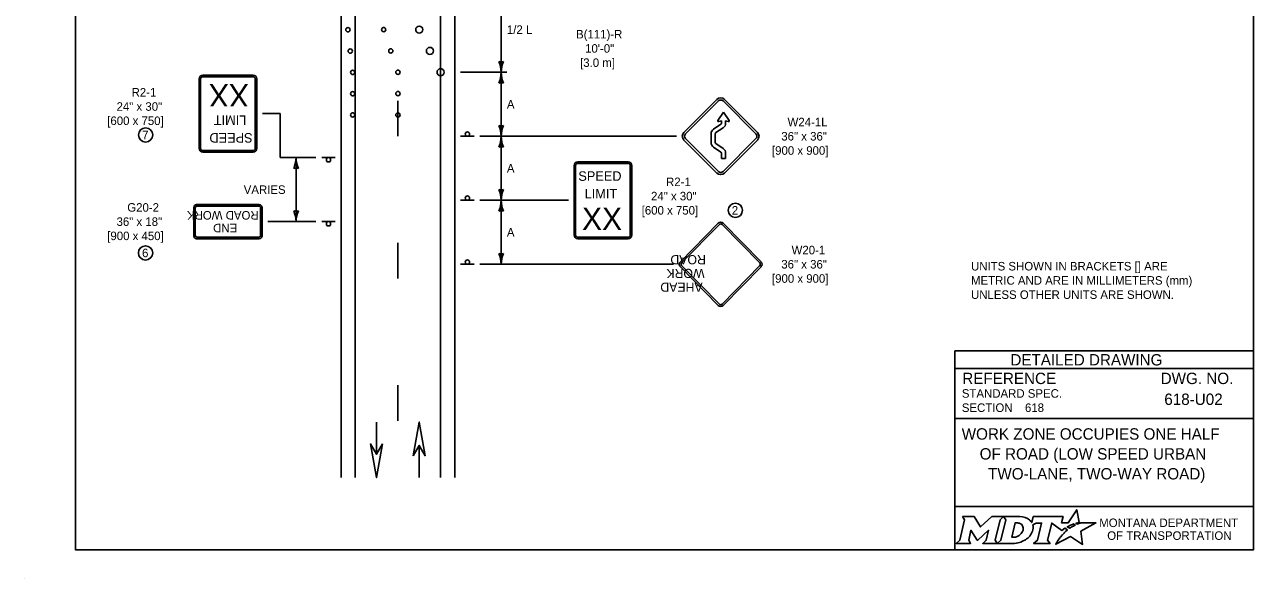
# Model space of a CAD drawing. Extents: x 49991.4 to 50021, y 49987.6 to 50011.4.
# Drawn here: x 49999.98 to 50008.61, y 49999.86 to 50003.76 of the extents above; entities that cross this region are included whole.
import ezdxf

# ---------------------------------------------------------------- set-up
doc = ezdxf.new("R2010")
doc.units = 0
for name, color, linetype in [('Level 1', 7, 'Continuous'), ('Level 2', 7, 'Continuous'), ('Level 3', 7, 'Continuous')]:
    doc.layers.add(name, color=color, linetype=linetype)

msp = doc.modelspace()

# ---------------------------------------------------------------- linework, layer by layer
at = {"layer": 'Level 1'}
for p, q in [((50002.201, 50000.5714), (50002.201, 50010.7538)), ((50002.301, 50000.5714), (50002.301, 50010.7538)), ((50003.001, 50000.5714), (50003.001, 50010.7538)), ((50002.901, 50000.5714), (50002.901, 50004.4714)), ((50001.2291, 50003.4006), (50001.5835, 50003.4006)), ((50001.2038, 50002.8858), (50001.2038, 50003.3753)), ((50001.2143, 50002.8858), (50001.2143, 50003.3753)), ((50001.2291, 50003.39), (50001.5835, 50003.39)), ((50001.5983, 50003.3753), (50001.5983, 50002.8858)), ((50001.6088, 50003.3753), (50001.6088, 50002.8858)), ((50002.601, 50002.9716), (50002.601, 50003.2216)), ((50004.8504, 50003.0834), (50004.8898, 50003.1407)), ((50004.8898, 50003.1407), (50004.9292, 50003.0834)), ((50004.819, 50003.0218), (50004.8711, 50003.0567)), ((50004.8748, 50003.0798), (50004.8571, 50003.0743)), ((50004.8748, 50003.0637), (50004.8748, 50003.0798)), ((50004.9225, 50003.0743), (50004.9048, 50003.0798)), ((50004.9048, 50003.0798), (50004.9048, 50003.0637)), ((50003.137, 50002.9714), (50003.041, 50002.9714)), ((50004.8019, 50002.9275), (50004.802, 50002.9898)), ((50004.8319, 50002.9898), (50004.8319, 50002.9274)), ((50004.8877, 50003.0318), (50004.8356, 50002.9969)), ((50004.8711, 50002.86), (50004.8187, 50002.8956)), ((50004.8356, 50002.9204), (50004.8879, 50002.8848)), ((50001.5835, 50002.8711), (50001.2291, 50002.8711)), ((50001.5835, 50002.8605), (50001.2291, 50002.8605)), ((50001.4063, 50002.8605), (50001.4063, 50002.8605)), ((50002.065, 50002.8211), (50002.161, 50002.8211)), ((50003.8649, 50002.7914), (50004.2194, 50002.7914)), ((50004.0421, 50002.7914), (50004.0421, 50002.7914)), ((50004.8748, 50002.8146), (50004.8748, 50002.8526)), ((50004.9048, 50002.8146), (50004.8748, 50002.8146)), ((50004.9048, 50002.8535), (50004.9048, 50002.8146)), ((50003.8396, 50002.2766), (50003.8396, 50002.7661)), ((50003.8502, 50002.2766), (50003.8502, 50002.7661)), ((50003.8649, 50002.7809), (50004.2194, 50002.7809)), ((50004.2341, 50002.7661), (50004.2341, 50002.2766)), ((50004.2447, 50002.7661), (50004.2447, 50002.2766)), ((50001.1661, 50002.2711), (50001.1661, 50002.4711)), ((50001.1761, 50002.2761), (50001.1761, 50002.4661)), ((50001.1862, 50002.4912), (50001.6262, 50002.4912)), ((50001.1911, 50002.4811), (50001.6211, 50002.4811)), ((50001.6361, 50002.4661), (50001.6361, 50002.2761)), ((50001.6461, 50002.4711), (50001.6461, 50002.2711)), ((50003.137, 50002.5214), (50003.041, 50002.5214)), ((50002.065, 50002.3711), (50002.161, 50002.3711)), ((50004.5865, 50002.0895), (50004.8517, 50002.3602)), ((50004.888, 50002.3602), (50005.1532, 50002.0895)), ((50004.5953, 50002.0809), (50004.8605, 50002.3515)), ((50004.8791, 50002.3515), (50005.1443, 50002.0809)), ((50001.1861, 50002.2511), (50001.6261, 50002.2511)), ((50001.1911, 50002.2611), (50001.6211, 50002.2611)), ((50002.601, 50001.9716), (50002.601, 50002.2216)), ((50004.2194, 50002.2619), (50003.8649, 50002.2619)), ((50004.2194, 50002.2513), (50003.8649, 50002.2513)), ((50003.137, 50002.0714), (50003.041, 50002.0714)), ((50004.8517, 50001.7826), (50004.5865, 50002.0533)), ((50004.8605, 50001.7913), (50004.5953, 50002.062)), ((50005.1443, 50002.062), (50004.8791, 50001.7913)), ((50005.1532, 50002.0533), (50004.888, 50001.7826)), ((50002.601, 50000.9716), (50002.601, 50001.2216)), ((50002.4507, 50000.9615), (50002.4507, 50000.7356)), ((50002.451, 50000.9615), (50002.451, 50000.7356)), ((50002.7504, 50000.5714), (50002.7504, 50000.7973)), ((50002.7507, 50000.5714), (50002.7507, 50000.7973)), ((49999.9766, 49999.8624), (49999.9766, 49999.8624))]:
    msp.add_line(p, q, dxfattribs=at)
for points in [[(50008.6146, 50011.2628), (50000.3356, 50011.2628), (50000.3356, 50000.0624), (50008.6146, 50000.0624)], [(50002.7087, 50000.725), (50002.7504, 50000.9615), (50002.7923, 50000.725), (50002.7504, 50000.7972)], [(50002.4927, 50000.8079), (50002.451, 50000.5714), (50002.4091, 50000.8079), (50002.451, 50000.7357)]]:
    msp.add_lwpolyline(points, close=True, dxfattribs=at)
for points in [[(50004.8429, 50003.2298), (50004.6113, 50002.9983)], [(50005.1283, 50002.9983), (50004.8967, 50003.2298)], [(50004.8533, 50003.2195), (50004.6217, 50002.9879)], [(50005.1179, 50002.9879), (50004.8864, 50003.2195)], [(50004.6113, 50002.9444), (50004.8429, 50002.7129)], [(50004.6217, 50002.9548), (50004.8533, 50002.7233)], [(50004.8864, 50002.7233), (50005.1179, 50002.9548)], [(50004.8967, 50002.7129), (50005.1283, 50002.9444)]]:
    msp.add_lwpolyline(points, dxfattribs=at)
for centre, radius in [((50002.751, 50003.7214), 0.025), ((50002.2493, 50003.7206), 0.015), ((50002.501, 50003.7214), 0.015), ((50002.266, 50003.5706), 0.015), ((50002.551, 50003.5714), 0.015), ((50002.826, 50003.5714), 0.025), ((50002.2827, 50003.4206), 0.015), ((50002.601, 50003.4214), 0.015), ((50002.901, 50003.4214), 0.025), ((50002.2827, 50003.2706), 0.015), ((50002.601, 50003.2714), 0.015), ((50002.2827, 50003.1214), 0.015), ((50002.601, 50003.1214), 0.015), ((50003.089, 50002.9867), 0.0152), ((50002.113, 50002.8059), 0.0152), ((50003.089, 50002.5367), 0.0152), ((50002.113, 50002.3559), 0.0152), ((50003.089, 50002.0866), 0.0152)]:
    msp.add_circle(centre, radius, dxfattribs=at)
for centre, radius, start, end in [((50002.751, 50003.7214), 0.025, 0, 180), ((50002.751, 50003.7214), 0.025, 180, 0), ((50002.826, 50003.5714), 0.025, 0, 180), ((50002.826, 50003.5714), 0.025, 180, 0), ((50001.2291, 50003.3753), 0.0253, 90, 180), ((50001.5835, 50003.3753), 0.0253, 360, 90), ((50002.901, 50003.4214), 0.025, 0, 180), ((50002.901, 50003.4214), 0.025, 180, 0), ((50001.2291, 50003.3753), 0.0148, 90, 180), ((50001.5835, 50003.3753), 0.0148, 360, 90), ((50004.8698, 50003.2029), 0.0381, 45, 135), ((50004.8698, 50003.2029), 0.0234, 45, 135), ((50004.8553, 50003.08), 0.00599, 145.48372, 287.36184), ((50004.8663, 50003.0637), 0.0085, 303.82394, 360), ((50004.8663, 50003.0637), 0.0384, 303.82395, 0), ((50004.9242, 50003.08), 0.00599, 252.63816, 34.51628), ((50004.6383, 50002.9714), 0.0381, 135, 225), ((50004.6383, 50002.9714), 0.0234, 135, 225), ((50004.8404, 50002.9898), 0.0384, 123.82394, 180), ((50004.8404, 50002.9898), 0.0085, 123.82391, 180), ((50005.1014, 50002.9714), 0.0234, 315, 45), ((50005.1014, 50002.9714), 0.0381, 315, 45), ((50001.2291, 50002.8858), 0.0253, 180, 270), ((50001.2291, 50002.8858), 0.0148, 180, 270), ((50001.5835, 50002.8858), 0.0148, 270, 360), ((50001.5835, 50002.8858), 0.0253, 270, 360), ((50004.8404, 50002.9274), 0.0384, 179.95178, 235.79051), ((50004.8404, 50002.9274), 0.0085, 179.94863, 235.79049), ((50004.8663, 50002.853), 0.0384, 0, 55.79052), ((50003.8649, 50002.7661), 0.0253, 90, 180), ((50004.2194, 50002.7661), 0.0253, 0, 90), ((50004.8663, 50002.853), 0.0085, 357.23622, 55.79052), ((50003.8649, 50002.7661), 0.0148, 90, 180), ((50004.2194, 50002.7661), 0.0148, 0, 90), ((50004.8698, 50002.7398), 0.0381, 225, 315), ((50004.8698, 50002.7398), 0.0234, 225, 315), ((50001.1862, 50002.4711), 0.02, 90, 180), ((50001.1911, 50002.4661), 0.015, 90, 180), ((50001.6211, 50002.4661), 0.015, 360, 90), ((50001.6262, 50002.4711), 0.02, 360, 90), ((50001.1911, 50002.2761), 0.015, 180, 270), ((50001.6211, 50002.2761), 0.015, 270, 360), ((50003.8649, 50002.2766), 0.0253, 180, 270), ((50003.8649, 50002.2766), 0.0148, 180, 270), ((50004.2194, 50002.2766), 0.0148, 270, 360), ((50004.2194, 50002.2766), 0.0253, 270, 360), ((50001.1861, 50002.2711), 0.02, 180, 270), ((50001.6261, 50002.2711), 0.02, 270, 360)]:
    msp.add_arc(centre, radius, start, end, dxfattribs=at)
for centre, major_axis, ratio, start_param, end_param in [((50004.8698, 50002.342), (0, 0.0258), 0.98963, 5.497787, 7.068583), ((50004.8698, 50002.342), (0, 0.0134), 0.98, 5.497787, 7.068583), ((50004.6046, 50002.0714), (0, 0.0258), 0.98963, 0.785394, 2.356194), ((50004.6046, 50002.0714), (0, 0.0134), 0.98, 0.785394, 2.356194), ((50005.1351, 50002.0714), (0, 0.0134), 0.98, 3.926991, 5.497787), ((50005.1351, 50002.0714), (0, 0.0258), 0.98963, 3.926991, 5.497787), ((50004.8698, 50001.8007), (0, -0.0258), 0.98963, 5.497795, 7.068583), ((50004.8698, 50001.8007), (0, -0.0134), 0.98, 5.497795, 7.068583)]:
    msp.add_ellipse(centre, major_axis=major_axis, ratio=ratio, start_param=start_param, end_param=end_param, dxfattribs=at)
at = {"layer": 'Level 2'}
for p, q in [((50008.6146, 50001.4624), (50006.5146, 50001.4624)), ((50006.5146, 50001.4624), (50006.5146, 50000.0624)), ((50008.6146, 50001.3374), (50006.5146, 50001.3374)), ((50008.2507, 50001.1223), (50008.2507, 50001.1223)), ((50008.6146, 50000.9874), (50006.5146, 50000.9874)), ((50007.0089, 50001.0629), (50007.0089, 50001.0629)), ((50007.5646, 50000.7383), (50007.5646, 50000.7383)), ((50008.6146, 50000.3693), (50006.5146, 50000.3693))]:
    msp.add_line(p, q, dxfattribs=at)
for points in [[(50006.5701, 50000.2974), (50006.5842, 50000.274), (50006.5507, 50000.1307), (50006.525, 50000.1082), (50006.6266, 50000.1082), (50006.6131, 50000.131), (50006.6293, 50000.2011), (50006.673, 50000.1321), (50006.6783, 50000.1321), (50006.7534, 50000.2016), (50006.737, 50000.1305), (50006.7123, 50000.1085), (50006.8139, 50000.1085), (50006.8001, 50000.1318), (50006.8333, 50000.2742)], [(50006.8333, 50000.2742), (50006.8586, 50000.2974), (50006.7762, 50000.2974), (50006.6966, 50000.2244), (50006.6521, 50000.2971), (50006.5701, 50000.2974)], [(50006.9722, 50000.2974), (50006.8586, 50000.2974), (50006.8733, 50000.2745), (50006.8394, 50000.1307), (50006.8139, 50000.1085), (50006.9245, 50000.1085)], [(50007.3771, 50000.2447), (50007.3668, 50000.2503), (50007.3784, 50000.2531), (50007.39, 50000.2551), (50007.3726, 50000.3452), (50007.3131, 50000.2539), (50007.2658, 50000.2532), (50007.2761, 50000.2973), (50007.0669, 50000.2974), (50007.0568, 50000.2549), (50007.051, 50000.2632)], [(50006.9962, 50000.2107), (50006.995, 50000.2026), (50006.9918, 50000.1933), (50006.9876, 50000.1851), (50006.982, 50000.1776), (50006.9755, 50000.1707), (50006.9676, 50000.1644), (50006.9593, 50000.1597), (50006.9502, 50000.1558), (50006.9411, 50000.1535), (50006.9319, 50000.1526), (50006.916, 50000.1526), (50006.9396, 50000.2526), (50006.9556, 50000.2526), (50006.9632, 50000.252), (50006.9708, 50000.2501), (50006.9774, 50000.2471), (50006.9835, 50000.2429), (50006.9883, 50000.2379), (50006.992, 50000.2319), (50006.9947, 50000.2257), (50006.9963, 50000.2183), (50006.9963, 50000.2153), (50006.9962, 50000.2107)], [(50007.0636, 50000.2383), (50007.0882, 50000.2514), (50007.1251, 50000.2514), (50007.0965, 50000.1309), (50007.069, 50000.1082), (50007.1852, 50000.1082), (50007.1682, 50000.1311), (50007.1964, 50000.2513), (50007.2677, 50000.1996), (50007.2888, 50000.2147), (50007.3085, 50000.2038)], [(50007.2527, 50000.1479), (50007.2374, 50000.1235), (50007.2327, 50000.116), (50007.2269, 50000.1074), (50007.2246, 50000.1031), (50007.3299, 50000.1562), (50007.4138, 50000.1011), (50007.4007, 50000.1938), (50007.5076, 50000.2522), (50007.4583, 50000.253), (50007.4282, 50000.2534), (50007.4074, 50000.2537), (50007.4006, 50000.2522), (50007.3957, 50000.251), (50007.3873, 50000.2487), (50007.3771, 50000.2447)], [(50007.3267, 50000.2171), (50007.3243, 50000.2154), (50007.306, 50000.225), (50007.3163, 50000.2307), (50007.3204, 50000.2329), (50007.329, 50000.2369), (50007.3347, 50000.2395), (50007.3426, 50000.2425), (50007.3499, 50000.2452), (50007.3617, 50000.2378), (50007.3577, 50000.2357), (50007.3531, 50000.2332), (50007.3489, 50000.231), (50007.3439, 50000.2281), (50007.342, 50000.227), (50007.3393, 50000.2254), (50007.3368, 50000.224), (50007.3345, 50000.2224), (50007.3319, 50000.2206), (50007.3292, 50000.2188), (50007.3267, 50000.2171)], [(50006.9702, 50000.1158), (50006.9786, 50000.1184), (50006.9916, 50000.1238), (50007.012, 50000.1348)], [(50007.2666, 50000.164), (50007.2666, 50000.164)]]:
    msp.add_lwpolyline(points, dxfattribs=at)
for centre, radius in [((50000.8271, 50002.9806), 0.05), ((50000.8271, 50002.9806), 0.05), ((50004.9733, 50002.4507), 0.0501), ((50000.827, 50002.151), 0.0501)]:
    msp.add_circle(centre, radius, dxfattribs=at)
for centre, radius, start, end in [((50006.9953, 50000.219), 0.0709, 339.53292, 15.85821), ((50006.9513, 50000.2363), 0.1183, 300.91025, 339.13831)]:
    msp.add_arc(centre, radius, start, end, dxfattribs=at)
for centre, major_axis, ratio, start_param, end_param in [((50006.9701, 50000.25), (0.0834, -0.0037), 0.568097, 0.61298, 1.570796), ((50007.0257, 50000.2573), (0.0361, -0.0295), 0.469099, 1.225588, 1.570796), ((50007.2974, 50000.1941), (-0.0112, -0.0097), 0.021651, 3.157348, 6.283185), ((50006.9248, 50000.2568), (0, 0.1484), 0.987302, 3.139398, 3.456847), ((50007.2597, 50000.1559), (-0.00694, -0.00806), 0.008222, 0, 3.137361), ((50007.2764, 50000.1742), (-0.0098, -0.0102), 0.016458, 3.141593, 6.279097)]:
    msp.add_ellipse(centre, major_axis=major_axis, ratio=ratio, start_param=start_param, end_param=end_param, dxfattribs=at)
at = {"layer": 'Level 3'}
for p, q in [((50003.327, 50003.4214), (50003.327, 50004.0214)), ((50003.041, 50003.4214), (50003.367, 50003.4214)), ((50003.327, 50002.9714), (50003.327, 50003.4214)), ((50001.6488, 50003.1306), (50001.7725, 50003.1306)), ((50001.7725, 50002.8211), (50001.7725, 50003.1306)), ((50003.177, 50002.9714), (50004.5602, 50002.9714)), ((50003.327, 50002.5214), (50003.327, 50002.9714)), ((50002.025, 50002.8211), (50001.7725, 50002.8211)), ((50001.885, 50002.3711), (50001.885, 50002.8211)), ((50003.177, 50002.5214), (50003.7996, 50002.5214)), ((50003.327, 50002.0714), (50003.327, 50002.5214)), ((50002.025, 50002.3711), (50001.6861, 50002.3711)), ((50003.177, 50002.0714), (50004.5391, 50002.0714))]:
    msp.add_line(p, q, dxfattribs=at)
for centre, radius, start, end in [((50003.327, 50003.5496), 0.0548, 252.13882, 287.86118), ((50003.0943, 50003.4099), 0.233, 2.82731, 22.07716), ((50003.5491, 50003.4122), 0.2223, 157.45601, 177.63952), ((50003.1049, 50003.4305), 0.2223, 337.45601, 357.63952), ((50003.5597, 50003.4329), 0.233, 182.82731, 202.07716), ((50003.327, 50003.2932), 0.0548, 72.13882, 107.86118), ((50003.327, 50003.0996), 0.0548, 252.13882, 287.86118), ((50003.0943, 50002.9599), 0.233, 2.82731, 22.07716), ((50003.1049, 50002.9805), 0.2223, 337.45601, 357.63952), ((50003.5491, 50002.9622), 0.2223, 157.45601, 177.63952), ((50003.5597, 50002.9829), 0.233, 182.82731, 202.07716), ((50003.327, 50002.8432), 0.0548, 72.13882, 107.86118), ((50001.6523, 50002.8326), 0.233, 337.92284, 357.17269), ((50002.1071, 50002.8303), 0.2223, 182.36048, 202.54399), ((50001.885, 50002.6929), 0.0548, 72.13882, 107.86118), ((50003.327, 50002.6496), 0.0548, 252.13882, 287.86118), ((50003.0943, 50002.5099), 0.233, 2.82731, 22.07716), ((50003.5491, 50002.5122), 0.2223, 157.45601, 177.63952), ((50001.6629, 50002.362), 0.2223, 2.36048, 22.54399), ((50001.885, 50002.4993), 0.0548, 252.13882, 287.86118), ((50002.1177, 50002.3596), 0.233, 157.92284, 177.17269), ((50003.1049, 50002.5305), 0.2223, 337.45601, 357.63952), ((50003.327, 50002.3932), 0.0548, 72.13882, 107.86118), ((50003.5597, 50002.5329), 0.233, 182.82731, 202.07716), ((50003.327, 50002.1996), 0.0548, 252.13882, 287.86118), ((50003.0943, 50002.0599), 0.233, 2.82731, 22.07716), ((50003.5491, 50002.0622), 0.2223, 157.45601, 177.63952)]:
    msp.add_arc(centre, radius, start, end, dxfattribs=at)

# ---------------------------------------------------------------- texts
at = {"layer": 'Level 1'}
for s, height, p in [('XX', 0.15772, (50001.5534, 50003.3395)), ('LIMIT', 0.06695, (50001.5351, 50003.1175)), ('SPEED', 0.06695, (50001.5794, 50002.9938)), ('ROAD WORK', 0.06, (50001.6219, 50002.4458)), ('END', 0.06, (50001.4713, 50002.3558)), ('ROAD', 0.06453, (50004.7656, 50002.1359)), ('WORK', 0.06453, (50004.7566, 50002.0392)), ('AHEAD', 0.06453, (50004.7428, 50001.9424))]:
    msp.add_text(s, height=height, rotation=180, dxfattribs=at).set_placement(p)
for s, height, p in [('SPEED', 0.06695, (50003.8691, 50002.6582)), ('LIMIT', 0.06695, (50003.9134, 50002.5344)), ('XX', 0.15772, (50003.8951, 50002.3124))]:
    msp.add_text(s, height=height, dxfattribs=at).set_placement(p)
at = {"layer": 'Level 2'}
for s, height, p in [('1/2 L', 0.06, (50003.367, 50003.6914)), ('B(111)-R', 0.06, (50003.8532, 50003.6591)), ('10\'-0"', 0.06, (50003.9167, 50003.5591)), ('[3.0 m]', 0.06, (50003.8815, 50003.4591)), ('R2-1', 0.06, (50000.7288, 50003.2506)), ('A', 0.06, (50003.367, 50003.1664)), ('24" x 30"', 0.06, (50000.6232, 50003.1506)), ('[600 x 750]', 0.06, (50000.5577, 50003.0506)), ('W24-1L', 0.06, (50005.3399, 50003.0414)), ('7', 0.06, (50000.8033, 50002.9506)), ('36" x 36"', 0.06, (50005.296, 50002.9414)), ('[900 x 900]', 0.06, (50005.2304, 50002.8414)), ('A', 0.06, (50003.367, 50002.7164)), ('VARIES', 0.06, (50001.517, 50002.5661)), ('R2-1', 0.06, (50004.4857, 50002.6207)), ('24" x 30"', 0.06, (50004.3801, 50002.5207)), ('G20-2', 0.06, (50000.6985, 50002.4411)), ('[600 x 750]', 0.06, (50004.3145, 50002.4207)), ('2', 0.06, (50004.9482, 50002.4207)), ('36" x 18"', 0.06, (50000.6232, 50002.3411)), ('[900 x 450]', 0.06, (50000.5577, 50002.2411)), ('A', 0.06, (50003.367, 50002.2664)), ('W20-1', 0.06, (50005.3683, 50002.1414)), ('6', 0.06, (50000.8024, 50002.121)), ('36" x 36"', 0.06, (50005.296, 50002.0414)), ('UNITS SHOWN IN BRACKETS [] ARE ', 0.06, (50006.6294, 50002.0278)), ('[900 x 900]', 0.06, (50005.2304, 50001.9414)), ('METRIC AND ARE IN MILLIMETERS (mm) ', 0.06, (50006.6294, 50001.9278)), ('UNLESS OTHER UNITS ARE SHOWN.', 0.06, (50006.6294, 50001.8278)), ('DETAILED DRAWING', 0.0799, (50006.9063, 50001.3599)), ('REFERENCE', 0.08, (50006.5682, 50001.229)), ('DWG. NO.', 0.08, (50007.9624, 50001.229)), ('STANDARD SPEC.', 0.06, (50006.5649, 50001.133)), ('618-U02', 0.08, (50007.9881, 50001.0823)), ('SECTION', 0.06, (50006.5649, 50001.033)), ('618', 0.06, (50007.0089, 50001.0329)), ('WORK ZONE OCCUPIES ONE HALF', 0.08, (50006.5641, 50000.8383)), ('OF ROAD (LOW SPEED URBAN', 0.08, (50006.6903, 50000.6983)), ('TWO-LANE, TWO-WAY ROAD)', 0.08, (50006.7495, 50000.5583)), ('MONTANA DEPARTMENT', 0.06, (50007.5308, 50000.2236)), ('OF TRANSPORTATION', 0.06, (50007.587, 50000.1336))]:
    msp.add_text(s, height=height, dxfattribs=at).set_placement(p)

doc.saveas('drawing.dxf')
